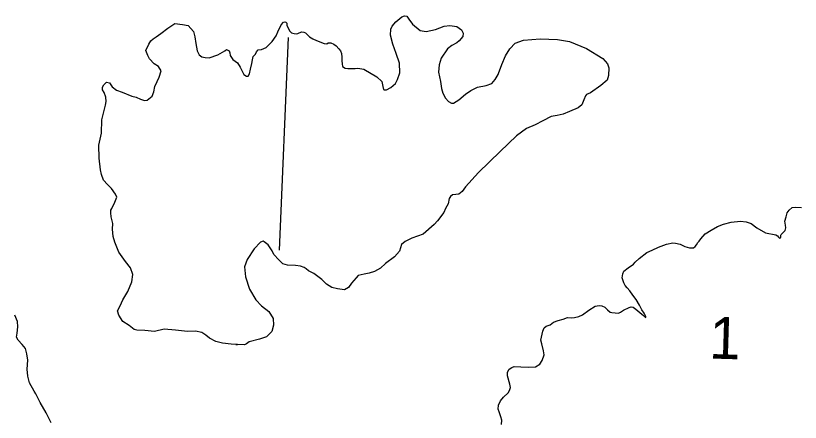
# Model space of a CAD drawing. Extents: x 653372 to 905732, y 627442 to 787275.
# Drawn here: x 712584 to 720498, y 736105 to 740207 of the extents above; entities that cross this region are included whole.
import ezdxf

# ---------------------------------------------------------------- set-up
doc = ezdxf.new("R2010")
doc.units = 0
doc.layers.add('5', color=7, linetype='Continuous')
doc.layers.add('9', color=7, linetype='Continuous')

msp = doc.modelspace()

# ---------------------------------------------------------------- linework, layer by layer
at = {"layer": '5'}
msp.add_lwpolyline([(715333.9, 739986.7), (715241.8, 737841)], dxfattribs=at)
at = {"layer": '9'}
for points in [[(716036.6, 739678.3), (716095.7, 739666.2), (716226.4, 739591.9), (716275.8, 739543.8), (716288.6, 739493.9), (716293.8, 739462.7), (716299.9, 739459.4), (716324.7, 739458.6), (716368.9, 739482.1), (716413.5, 739524.2), (716436.4, 739563.9), (716457.1, 739631.5), (716456.9, 739727.7), (716422.6, 739825), (716388.2, 739919.1), (716363, 740009.8), (716367.9, 740071.7), (716381.3, 740102.4), (716419.8, 740144.6), (716480.2, 740195.6), (716505.4, 740207.2), (716530.1, 740203.4), (716550.9, 740171.7), (716586.6, 740121), (716662.2, 740056.7), (716724, 740048.6), (716817.6, 740067.5), (716905.5, 740102.1), (716961.6, 740109.8), (717032.6, 740098.3), (717081.2, 740065.8), (717098.8, 740031.2), (717094.7, 739997.2), (717056.2, 739954.9), (717033.8, 739933.8), (716983.4, 739907.4), (716938.9, 739871.5), (716877.1, 739777.2), (716856.6, 739712.6), (716848.1, 739638.4), (716870, 739541.6), (716880.4, 739473), (716891.4, 739426.1), (716917.8, 739375.7), (716950.9, 739340.5), (716978.3, 739324.2), (717000, 739323.6), (717053.8, 739359.2), (717120.6, 739416.1), (717174.4, 739451.7)], [(713458.2, 739459), (713459.1, 739486.9), (713472.2, 739511.3), (713500.9, 739535.3), (713528.6, 739530.7), (713558.4, 739490.1), (713600.8, 739454.7), (713659.1, 739434.4), (713754.1, 739394.3), (713800.4, 739386.7), (713843.1, 739363.7), (713883.1, 739353.2), (713911.1, 739355.4), (713958.8, 739394.3), (713975.7, 739440.4), (713986.6, 739492.8), (714009.8, 739541.7), (714029.8, 739587.7), (714050.3, 739651.9), (714023.7, 739696.2), (713981.1, 739722.3), (713932.9, 739770.3), (713915.3, 739804.9), (713898.2, 739855.1), (713928, 739919), (713947.7, 739952.6), (713970, 739973.6), (714001.7, 739994.4), (714049.2, 740027.1), (714119, 740080.8), (714188.7, 740128.4), (714266, 740119.9), (714324.6, 740108.8), (714378.6, 740048.2), (714389.4, 739995.2), (714399.8, 739926.6), (714413, 739851.7), (714433.5, 739810.8), (714460.8, 739791.3), (714494.7, 739784.1), (714535, 739782.9), (714622.7, 739811.3), (714692.2, 739852.6), (714711.2, 739864.5), (714738.8, 739854.3), (714744.4, 739832.4), (714746.6, 739804.5), (714773.4, 739766.4), (714822, 739730.8), (714848.5, 739686.6), (714874.9, 739633), (714883.6, 739614.2), (714911, 739597.8), (714929.6, 739597.3), (714942.8, 739621.7), (714953.4, 739667.9), (714964.4, 739723.4), (714971.7, 739760.5), (714979, 739794.4), (715001.4, 739818.5), (715014.5, 739843), (715030.6, 739861.1), (715061.8, 739866.4), (715108.9, 739886.7), (715169.7, 739946.9), (715211.7, 740004.6), (715228.4, 740044.4)], [(715228.4, 740044.4), (715261.9, 740114.1), (715286.2, 740141.8), (715298, 740144.8), (715309.5, 740141.1), (715317.6, 740130.8), (715320.3, 740110.7), (715347.1, 740054.7), (715364.9, 740035.8), (715391.3, 740026.7), (715416.3, 740022.6), (715431.5, 740028.8), (715467, 740042.8), (715490.4, 740042.1), (715508.5, 740033.2), (715528, 740014.2), (715547.4, 739993.6), (715580.2, 739972.5), (715618.2, 739958), (715694.1, 739927.3), (715720.8, 739924.8), (715734.5, 739934.5), (715761.1, 739932), (715792.5, 739919.3), (715817.1, 739903.6), (715842.9, 739874.4), (715859, 739852.1), (715869.9, 739825.1), (715873.8, 739788.2), (715872.7, 739753.1), (715876.8, 739722.9), (715881, 739696), (715905.6, 739678.6), (715933.9, 739676.1), (716007.4, 739673.9), (716036.6, 739678.3)], [(717174.4, 739451.7), (717243.7, 739486.9), (717328, 739503), (717387.5, 739522.9), (717419.7, 739562.3), (717449.2, 739614.2), (717452.6, 739623.4), (717486.3, 739715.4), (717526.1, 739801.1), (717568.7, 739874.3), (717623, 739928.5), (717707.7, 739960.1), (717875.6, 739973.7), (718049.2, 739968.5), (718169.5, 739946.3), (718341.1, 739875.9), (718505.6, 739774.8), (718553.6, 739720.6), (718567.9, 739679.9), (718562.4, 739602.4), (718548.6, 739556.3), (718485, 739502.4), (718380.4, 739427.9), (718342.6, 739410.5), (718329.9, 739398.4), (718316.3, 739358.5), (718296.1, 739306.4), (718258, 739276.5), (718170.1, 739241.9), (718107.1, 739212.7), (718044.7, 739199.1), (717985.4, 739188.5), (717900.5, 739147.6), (717824.8, 739106.4), (717736.8, 739068.7), (717635.3, 738994.2), (717472.4, 738837.7), (717250.8, 738625.2), (717120.5, 738482.2), (717088, 738433.5), (717053.1, 738406.6), (717025.1, 738404.3), (716990.8, 738399.2), (716968.7, 738384.3), (716955.6, 738363), (716944.8, 738310.6), (716918.5, 738261.7), (716901.8, 738221.9), (716837.2, 738136.9), (716805.1, 738100.7), (716693.5, 738002.5), (716580.7, 737962.4)], [(714805.4, 736891.2), (714821.7, 736890.2), (714757.7, 736893.5), (714670.4, 736904.6), (714602.6, 736919), (714538.5, 736955.1), (714502.2, 736984.1), (714462.6, 737010.1), (714397.9, 737024.5), (714317.2, 737020.7), (714195, 737033.7), (714080.5, 737043.3), (713983.7, 737021.4), (713887.8, 737030.5), (713807.4, 737036), (713779.6, 737039.9), (713728.1, 737081.8), (713664.1, 737121), (713622.7, 737187.4), (713611.5, 737228), (713637.9, 737280), (713664.5, 737341.3), (713713.5, 737423.6), (713753.7, 737521.7), (713765.2, 737595.8), (713742.5, 737664.7), (713691.7, 737728.3), (713623.1, 737820.4), (713582.7, 737920.9), (713565.8, 737980.3), (713561.9, 738054.9), (713563.6, 738110.7), (713547.6, 738177.9), (713542.6, 738218.4), (713544.3, 738244.1), (713552, 738261.9), (713584.9, 738325.7), (713602.5, 738375.8), (713591.1, 738407.3), (713549.4, 738464.4), (713510.2, 738502.9), (713468.1, 738547.6), (713448.1, 738604), (713440.2, 738650.8), (713425.2, 738770.5), (713422.9, 738902.2), (713448.2, 739022.4), (713452.2, 739155.1), (713490.9, 739306), (713495, 739340), (713493.3, 739386.6), (713476.1, 739433.7), (713458.2, 739459)], [(719663.6, 738081.4), (719723.9, 738104.5), (719799.4, 738123.1), (719895.3, 738132.7), (719953.4, 738126.8), (720002.8, 738110), (720059.8, 738065.3), (720147, 738015.5), (720251.9, 737997.1), (720268.2, 737986.9), (720277.4, 737971.4), (720284.2, 737965.6), (720292.4, 737962.6), (720298.1, 737965.2), (720302.6, 737977.5), (720303.1, 737992.8), (720304.7, 738001.1), (720321.8, 738017.2), (720344.7, 738041.5), (720352.5, 738067.6), (720350.5, 738094), (720343.3, 738133.1), (720355.7, 738177.1), (720366.7, 738218.4), (720386.9, 738244.2), (720415.5, 738272.4), (720454.4, 738276.8), (720509.8, 738272.4)], [(717484.9, 736082.3), (717489, 736125.2), (717478.9, 736158.8), (717459.6, 736209.3), (717449.4, 736238.7), (717454.7, 736277.4), (717475.5, 736321.2), (717505.7, 736359.1), (717552.8, 736402.1), (717566, 736425.3), (717573.8, 736455.6), (717569.3, 736489), (717544.1, 736574.4), (717545.2, 736610.5), (717561.3, 736640.5), (717586.9, 736659.1), (717613.4, 736666.7), (717678.5, 736663.3), (717760.3, 736662.3), (717826.9, 736663.8), (717869.3, 736690.3), (717895.5, 736729.7), (717915.2, 736784.6), (717909.4, 736825), (717890.8, 736896.4), (717879.4, 736934.2), (717900.2, 737025.1), (717915.1, 737059.3), (717933.6, 737074), (717975.6, 737089.4), (718008.3, 737114.8), (718057.4, 737132.8), (718104.9, 737145.2), (718149.8, 737163.3), (718192.7, 737160.6), (718220.5, 737162.5), (718265.2, 737172.3), (718300, 737190.4), (718365.2, 737237), (718430.2, 737275.3), (718467.9, 737283.9), (718496.9, 737281.6), (718526.9, 737265.4), (718552.5, 737238.3), (718580.9, 737216.6), (718598.8, 737211.9), (718632.1, 737210.9), (718663.9, 737207.2), (718684.9, 737214.9), (718716.1, 737236.2), (718771, 737263.6), (718793.4, 737271.3), (718811.3, 737266.6), (718839.8, 737246.3), (718878.7, 737211.8), (718918.1, 737182.9), (718934.2, 737165.7), (718939.6, 737162.8), (718941, 737161.4), (718939.9, 737172.5), (718923, 737207.7), (718900.4, 737240.3), (718875.4, 737286.8), (718842.4, 737343.3), (718810.5, 737388.6), (718779.8, 737429.8), (718753.1, 737461.1), (718732.7, 737486), (718716.9, 737512.8), (718701.7, 737561.9), (718707.1, 737601.9), (718719, 737630.7), (718760.3, 737664.2), (718816.8, 737699.9), (718832.7, 737721.6), (718872.6, 737756.5), (718949.3, 737816.6), (719002.7, 737840), (719068.8, 737871.3), (719150.1, 737900.8), (719213, 737915.5), (719240.7, 737913.3), (719286.1, 737903.6), (719334, 737880), (719380.7, 737864.7), (719422, 737866.1), (719439.4, 737879.6), (719449.6, 737895.9), (719465.5, 737917.7), (719478.4, 737933.9), (719495.5, 737955.5), (719538.8, 738005.6), (719597.9, 738042.6), (719663.6, 738081.4)], [(716580.7, 737962.4), (716511.5, 737930.4), (716476.4, 737897.3), (716455.8, 737832.7), (716404.5, 737775.3), (716315.5, 737706.6), (716264.6, 737661.6), (716201.5, 737626.3), (716148.2, 737609.2), (716098.3, 737598.3), (716039, 737587.7), (716019.7, 737563.5), (715971.5, 737509.1), (715942.2, 737463.4), (715901.3, 737442.9), (715830.2, 737451.2), (715771.7, 737465.4), (715719.9, 737498), (715671.7, 737546), (715591.1, 737607.4), (715536, 737633.8), (715514.9, 737653.1), (715493.6, 737666.1), (715456.7, 737679.7), (715407.3, 737687.3), (715326.8, 737689.8), (715277.5, 737703.7), (715238.5, 737745.2), (715187.3, 737796.4), (715169.8, 737834.1), (715131.3, 737894.2), (715091.9, 737926.4), (715079.7, 737933), (715054.5, 737921.3), (714989.8, 737854.9), (714918.3, 737748.5), (714892, 737674.9), (714901.4, 737572.2), (714941, 737446.9), (715006, 737339.5), (715064.2, 737280.7), (715135.9, 737222.6), (715180.4, 737153), (715184.5, 737084.6), (715167.1, 737020), (715112.7, 736965.8), (715043.8, 736943), (714937.3, 736916.5), (714911.6, 736896.1), (714891.2, 736885.9), (714821.7, 736890.2)], [(712597.2, 737003.1), (712607.1, 737068.4), (712600.8, 737121.1), (712573.8, 737184.9)], [(712941.8, 736100.9), (712892.4, 736202.1), (712829.9, 736306.3), (712787.9, 736391.5), (712770.4, 736420.2), (712723.1, 736502.9), (712706.8, 736571.6), (712698.4, 736642.7), (712706.3, 736731.7), (712697.7, 736794.9), (712683.7, 736850.4), (712649, 736891.4), (712608.2, 736932), (712590.8, 736964), (712597.2, 737003.1)]]:
    msp.add_lwpolyline(points, dxfattribs=at)

# ---------------------------------------------------------------- texts
at = {"layer": '5'}
msp.add_text('1', height=422.4, rotation=358.28003, dxfattribs=at).set_placement((719575.5, 736749.1))

doc.saveas('drawing.dxf')
